Omron CX-Programmer project NewProject (CX-Programmer 6.11)

# PLC NewPLC1: CPM2* 

## Global symbols (name address type ; comment)
0.00 BOOL  ; Törlés
AR8.00 BOOL  ; Normális
AR8.01 BOOL  ; paritáshiba
AR8.02 BOOL  ; Formátumhiba
AR8.03 BOOL  ; Túlcsordulás
AR8.08 BOOL  ; Normális
AR8.09 BOOL  ; Paritás hiba
AR8.10 BOOL  ; Formátum hiba
AR8.11 BOOL  ; túlcsordulás
DM0 CHANNEL  ; uc Parancs

## Program NewProgram1 (no task)

### Section Section1

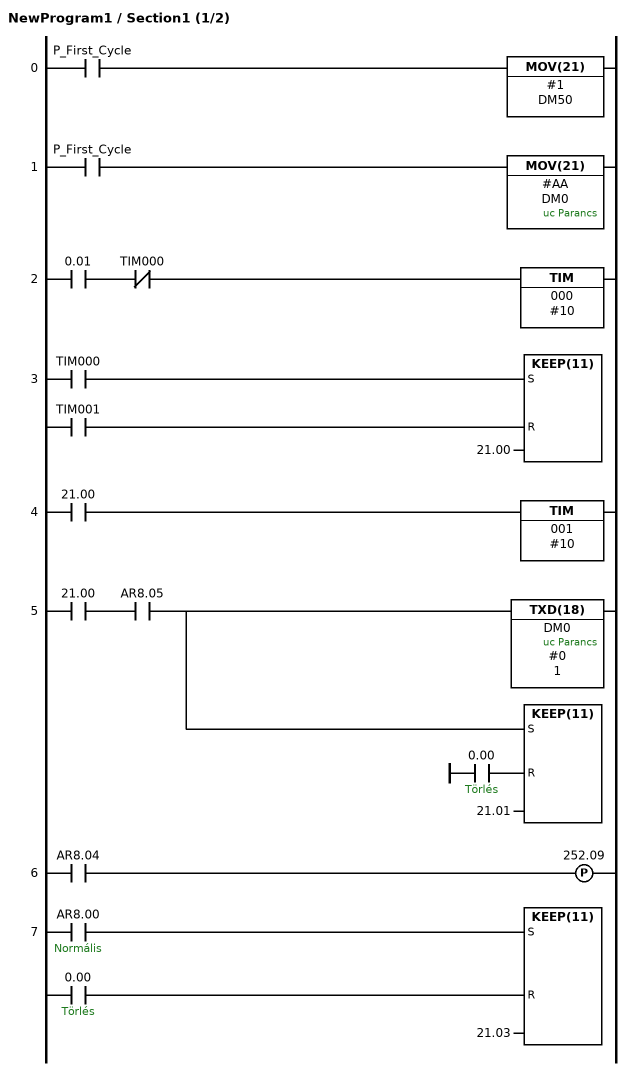
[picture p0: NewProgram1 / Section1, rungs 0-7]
; rung 0
LD P_First_Cycle
MOV(21) #1 DM50
; rung 1
LD P_First_Cycle
MOV(21) #AA DM0  ; uc Parancs
; rung 2
LD 0.01
ANDNOT TIM000
TIM 000 #10
; rung 3
LD TIM000
LD TIM001
KEEP(11) 21.00
; rung 4
LD 21.00
TIM 001 #10
; rung 5
LD 21.00
AND AR8.05
TXD(18) DM0 #0 1  ; uc Parancs
LD 0.00  ; Törlés
KEEP(11) 21.01
; rung 6
LD AR8.04
DIFU(13) 252.09
; rung 7
LD AR8.00  ; Normális
LD 0.00  ; Törlés
KEEP(11) 21.03

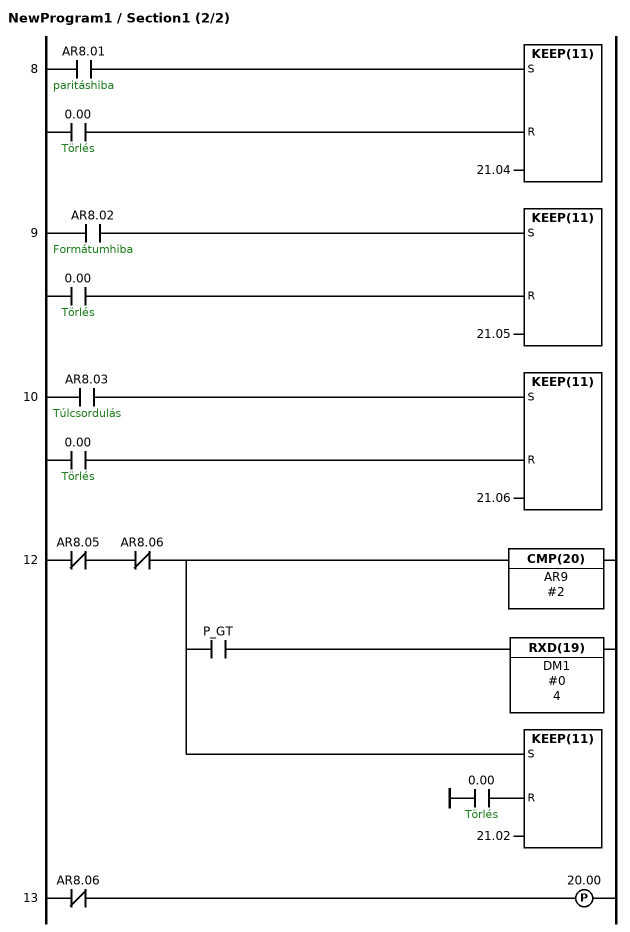
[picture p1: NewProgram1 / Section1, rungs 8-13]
; rung 8
LD AR8.01  ; paritáshiba
LD 0.00  ; Törlés
KEEP(11) 21.04
; rung 9
LD AR8.02  ; Formátumhiba
LD 0.00  ; Törlés
KEEP(11) 21.05
; rung 10
LD AR8.03  ; Túlcsordulás
LD 0.00  ; Törlés
KEEP(11) 21.06
; rung 12
LDNOT AR8.05
ANDNOT AR8.06
OUT TR0
CMP(20) AR9 #2
AND P_GT
RXD(19) DM1 #0 4
LD TR0
LD 0.00  ; Törlés
KEEP(11) 21.02
; rung 13
LDNOT AR8.06
DIFU(13) 20.00
; rung 14
END(01)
